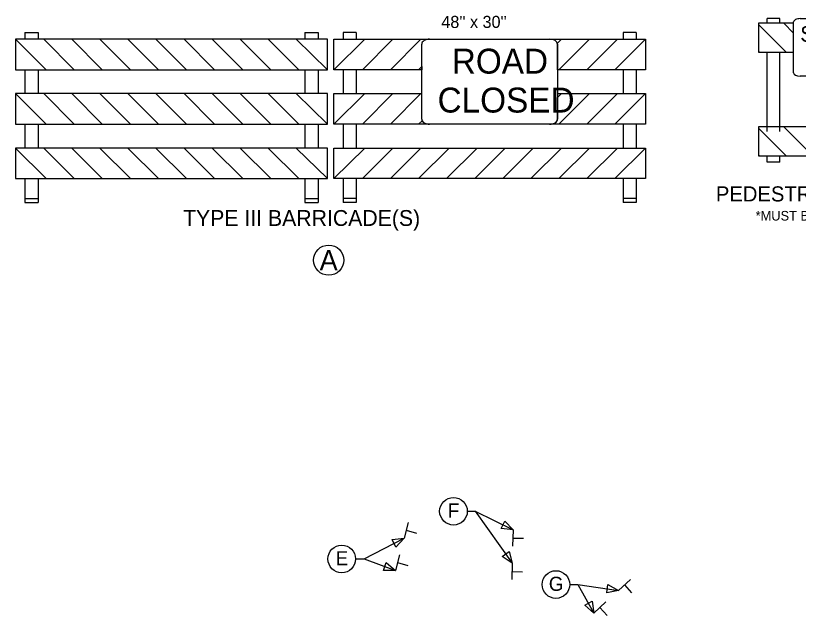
# Model space of a CAD drawing. Extents: x 2157572 to 5059327, y 715220 to 1674494.
# Drawn here: x 2159643 to 2163528, y 715966 to 718941 of the extents above; entities that cross this region are included whole.
import ezdxf

# ---------------------------------------------------------------- set-up
doc = ezdxf.new("R2010")
doc.units = 0
for name, color, linetype in [('Exist Cultural Church Label', 7, 'Continuous'), ('Exist Hydrographic Creek Single Shore Label', 7, 'Continuous'), ('Exist Road Primary US Structure Standard Bridge Number Label', 7, 'Continuous'), ('Exist Road Secondary Structure Culvert Number Label', 7, 'Continuous'), ('Level 51', 7, 'Continuous'), ('Map Preparation County Base Legend Hangar on Field', 7, 'Continuous'), ('Map Preparation County Base Legend Highway Garage or Maintenance Office', 7, 'Continuous'), ('Map Preparation County Base Legend Marked Auxillary Field', 7, 'Continuous'), ('Map Preparation County Base Legend Rest Area', 7, 'Continuous'), ('Map Preparation County North Arrow Shadow', 7, 'Continuous')]:
    doc.layers.add(name, color=color, linetype=linetype)

# ---------------------------------------------------------------- blocks, each defined once
blk = doc.blocks.new('PEDBARRSWCLOSED')
at = {"layer": 'Map Preparation County Base Legend Hangar on Field'}
for p, q in [((26.5, 0), (0, 0)), ((0, 0), (-26.5, 0))]:
    blk.add_line(p, q, dxfattribs=at)
for points in [[(-26.5, 30), (0, 30)], [(0, 30), (26.5, 30)], [(-30, 1.75), (-30, 28.25)], [(30, 28.25), (30, 1.75)]]:
    blk.add_lwpolyline(points, dxfattribs=at)
for centre, major_axis, start_param, end_param in [((-26.5, 28.25), (-3.5, 0), 4.712162, 6.283185), ((26.5, 28.25), (3.5, 0), 0, 1.570796), ((-26.5, 1.75), (-3.5, 0), 0, 1.570796), ((26.5, 1.75), (-3.5, 0), 1.570796, 3.141593)]:
    blk.add_ellipse(centre, major_axis=major_axis, ratio=0.5, start_param=start_param, end_param=end_param, dxfattribs=at)
at = {"layer": 'Map Preparation County Base Legend Marked Auxillary Field'}
for p, q in [((-37.19, 30), (-43.76, 30)), ((-43.76, 27.64), (-43.76, 30)), ((-37.19, 27.64), (-37.19, 30)), ((43.76, 30), (37.19, 30)), ((37.19, 27.64), (37.19, 30)), ((43.76, 27.64), (43.76, 30.06)), ((-48.36, 27.64), (-48.36, 12.46)), ((-30, 27.64), (-48.36, 27.64)), ((-35.14, 27.64), (-48.36, 27.64)), ((-30, 22.5), (-35.14, 27.64)), ((30, 21.58), (36.06, 27.64)), ((48.36, 27.64), (30, 27.64)), ((36.06, 27.64), (48.36, 27.64)), ((48.36, 12.46), (48.36, 27.64)), ((-47.82, 12.46), (-48.36, 13.01)), ((-48.36, 12.46), (-47.82, 12.46)), ((-48.36, 12.46), (-30, 12.46)), ((-43.76, -14.53), (-43.76, 12.46)), ((-37.19, -14.53), (-37.19, 12.46)), ((30, 12.46), (48.36, 12.46)), ((37.19, -14.53), (37.19, 12.46)), ((43.76, -14.53), (43.76, 12.46)), ((-43.76, -28.8), (-43.76, -14.53)), ((-37.19, -28.7), (-37.19, -14.53)), ((37.19, -33.18), (37.19, -14.53)), ((43.76, -32.25), (43.76, -14.53)), ((-48.36, -26.35), (-48.36, -41.53)), ((48.36, -26.35), (-48.36, -26.35)), ((-35.14, -26.35), (-48.36, -26.35)), ((-19.97, -41.53), (-35.14, -26.35)), ((-6.04, -41.53), (-21.21, -26.35)), ((-21.21, -26.35), (-7.29, -26.35)), ((-7.29, -26.35), (0.46, -34.1)), ((0.46, -34.1), (8.21, -26.35)), ((22.13, -26.35), (6.96, -41.53)), ((8.21, -26.35), (22.13, -26.35)), ((20.89, -41.53), (36.06, -26.35)), ((36.06, -26.35), (48.36, -26.35)), ((48.36, -41.53), (48.36, -26.35)), ((65.44, -34.49), (65.44, -41.53)), ((-47.82, -41.53), (-48.36, -40.98)), ((-48.36, -41.53), (-47.82, -41.53)), ((-48.36, -41.53), (48.36, -41.53)), ((-43.76, -44.81), (-43.76, -41.53)), ((-37.19, -44.81), (-43.76, -44.81)), ((-37.19, -44.81), (-37.19, -41.53)), ((-33.89, -41.53), (-19.97, -41.53)), ((6.96, -41.53), (-6.96, -41.53)), ((34.81, -41.53), (20.89, -41.53)), ((37.19, -44.81), (37.19, -41.53)), ((43.76, -44.81), (37.19, -44.81)), ((43.76, -44.81), (43.76, -41.53)), ((51.11, -44.81), (66.83, -44.81)), ((53.37, -41.53), (66.83, -41.53)), ((65.44, -44.81), (65.44, -51.17))]:
    blk.add_line(p, q, dxfattribs=at)
for points in [[(-48.36, 27.64), (-48.36, 26.93), (-33.89, 12.46)], [(48.36, 27.64), (48.36, 26.01), (34.81, 12.46)], [(-33.89, 12.46), (-30, 12.46), (-30, 22.5)], [(34.81, 12.46), (30, 12.46), (30, 21.58)], [(-48.36, -26.35), (-48.36, -27.06), (-33.89, -41.53)], [(48.36, -26.35), (48.36, -27.98), (34.81, -41.53)]]:
    blk.add_lwpolyline(points, dxfattribs=at)
at = {"layer": 'Map Preparation County Base Legend Hangar on Field'}
for s, p in [('SIDEWALK', (-26.54, 17.9)), ('CLOSED', (-21.11, 4.07))]:
    blk.add_text(s, height=8.172, dxfattribs=at).set_placement(p)
at = {"layer": 'Map Preparation County Base Legend Marked Auxillary Field'}
for s, height, p in [('2" MAX', 6, (70.36, -45.51)), ('PEDESTRIAN BARRICADE', 7.8816, (-70.5, -65.23)), ('*MUST BE ADA-COMPLIANT*', 5, (-49.77, -75.16))]:
    blk.add_text(s, height=height, dxfattribs=at).set_placement(p)

msp = doc.modelspace()

# ---------------------------------------------------------------- linework, layer by layer
at = {"layer": 'Exist Cultural Church Label'}
for centre in [(2161816.1, 716482.5), (2161261.4, 716246), (2162324.6, 716119)]:
    msp.add_circle(centre, 68.6, dxfattribs=at)
at = {"layer": 'Exist Road Secondary Structure Culvert Number Label'}
for p, q in [((2159688.5, 718856.9), (2159754.2, 718856.9)), ((2159688.5, 718856.9), (2159688.5, 718824)), ((2159754.2, 718856.9), (2159754.2, 718824)), ((2161078.3, 718856.9), (2161144, 718856.9)), ((2161078.3, 718856.9), (2161078.3, 718824)), ((2161144, 718856.9), (2161144, 718824)), ((2161333.6, 718856.9), (2161267.9, 718856.9)), ((2161267.9, 718856.9), (2161267.9, 718824)), ((2161333.6, 718856.9), (2161333.6, 718824)), ((2162723.4, 718856.9), (2162657.7, 718856.9)), ((2162657.7, 718856.9), (2162657.7, 718824)), ((2162723.4, 718856.9), (2162723.4, 718824)), ((2161190, 718824), (2159642.5, 718824)), ((2159642.5, 718824), (2159642.5, 718672.3)), ((2159781.8, 718824), (2159642.5, 718824)), ((2159642.5, 718824), (2159794.3, 718672.3)), ((2159933.5, 718672.3), (2159781.8, 718824)), ((2160060.3, 718824), (2159921, 718824)), ((2159921, 718824), (2160072.7, 718672.3)), ((2160212, 718672.3), (2160060.3, 718824)), ((2160338.7, 718824), (2160199.5, 718824)), ((2160199.5, 718824), (2160351.2, 718672.3)), ((2160490.5, 718672.3), (2160338.7, 718824)), ((2160617.9, 718824), (2160478.6, 718824)), ((2160478.6, 718824), (2160630.4, 718672.3)), ((2160769.6, 718672.3), (2160617.9, 718824)), ((2160896.4, 718824), (2160757.1, 718824)), ((2160757.1, 718824), (2160908.8, 718672.3)), ((2161048.1, 718672.3), (2160896.4, 718824)), ((2161190, 718824), (2161035.6, 718824)), ((2161035.6, 718824), (2161190, 718672.3)), ((2161190, 718672.3), (2161190, 718824)), ((2161190, 718672.3), (2161190, 718824)), ((2161221.9, 718824), (2162769.4, 718824)), ((2161221.9, 718672.3), (2161221.9, 718824)), ((2161221.9, 718672.3), (2161221.9, 718824)), ((2161221.9, 718824), (2161376.3, 718824)), ((2161376.3, 718824), (2161221.9, 718672.3)), ((2161363.8, 718672.3), (2161515.5, 718824)), ((2161654.8, 718824), (2161503, 718672.3)), ((2161515.5, 718824), (2161654.8, 718824)), ((2162332.1, 718804.5), (2162351.6, 718824)), ((2162490.9, 718824), (2162339.2, 718672.3)), ((2162351.6, 718824), (2162490.9, 718824)), ((2162478.4, 718672.3), (2162630.1, 718824)), ((2162769.4, 718824), (2162617.6, 718672.3)), ((2162630.1, 718824), (2162769.4, 718824)), ((2162769.4, 718824), (2162769.4, 718672.3)), ((2162333, 718672.3), (2162333, 718799.5)), ((2159642.5, 718672.3), (2161190, 718672.3)), ((2159688.5, 718672.3), (2159688.5, 718554.1)), ((2159754.2, 718672.3), (2159754.2, 718554.1)), ((2159794.3, 718672.3), (2159933.5, 718672.3)), ((2160072.7, 718672.3), (2160212, 718672.3)), ((2160351.2, 718672.3), (2160490.5, 718672.3)), ((2160630.4, 718672.3), (2160769.6, 718672.3)), ((2160908.8, 718672.3), (2161048.1, 718672.3)), ((2161078.3, 718672.3), (2161078.3, 718554.1)), ((2161144, 718672.3), (2161144, 718554.1)), ((2161658.3, 718672.3), (2161221.9, 718672.3)), ((2161267.9, 718672.3), (2161267.9, 718554.1)), ((2161333.6, 718672.3), (2161333.6, 718554.1)), ((2161503, 718672.3), (2161363.8, 718672.3)), ((2161642.3, 718672.3), (2161658.3, 718688.3)), ((2161658.3, 718672.3), (2161642.3, 718672.3)), ((2161658.3, 718688.3), (2161658.3, 718672.3)), ((2162339.2, 718672.3), (2162333, 718672.3)), ((2162769.4, 718672.3), (2162333, 718672.3)), ((2162617.6, 718672.3), (2162478.4, 718672.3)), ((2162657.7, 718672.3), (2162657.7, 718554.1)), ((2162723.4, 718672.3), (2162723.4, 718554.1)), ((2161190, 718554.1), (2159642.5, 718554.1)), ((2159642.5, 718554.1), (2159642.5, 718402.4)), ((2159781.8, 718554.1), (2159642.5, 718554.1)), ((2159642.5, 718554.1), (2159794.3, 718402.4)), ((2159933.5, 718402.4), (2159781.8, 718554.1)), ((2160060.3, 718554.1), (2159921, 718554.1)), ((2159921, 718554.1), (2160072.7, 718402.4)), ((2160212, 718402.4), (2160060.3, 718554.1)), ((2160338.7, 718554.1), (2160199.5, 718554.1)), ((2160199.5, 718554.1), (2160351.2, 718402.4)), ((2160490.5, 718402.4), (2160338.7, 718554.1)), ((2160617.9, 718554.1), (2160478.6, 718554.1)), ((2160478.6, 718554.1), (2160630.4, 718402.4)), ((2160769.6, 718402.4), (2160617.9, 718554.1)), ((2160896.4, 718554.1), (2160757.1, 718554.1)), ((2160757.1, 718554.1), (2160908.8, 718402.4)), ((2161048.1, 718402.4), (2160896.4, 718554.1)), ((2161190, 718554.1), (2161035.6, 718554.1)), ((2161035.6, 718554.1), (2161190, 718402.4)), ((2161190, 718402.4), (2161190, 718554.1)), ((2161190, 718402.4), (2161190, 718554.1)), ((2161221.9, 718402.4), (2161221.9, 718554.1)), ((2161221.9, 718402.4), (2161221.9, 718554.1)), ((2161221.9, 718554.1), (2161376.3, 718554.1)), ((2161376.3, 718554.1), (2161221.9, 718402.4)), ((2161221.9, 718554.1), (2161658.3, 718554.1)), ((2161363.8, 718402.4), (2161515.5, 718554.1)), ((2161654.8, 718554.1), (2161503, 718402.4)), ((2161515.5, 718554.1), (2161654.8, 718554.1)), ((2162333, 718535.4), (2162351.6, 718554.1)), ((2162333, 718554.1), (2162769.4, 718554.1)), ((2162333, 718427), (2162333, 718535.4)), ((2162490.9, 718554.1), (2162339.2, 718402.4)), ((2162351.6, 718554.1), (2162490.9, 718554.1)), ((2162478.4, 718402.4), (2162630.1, 718554.1)), ((2162769.4, 718554.1), (2162617.6, 718402.4)), ((2162630.1, 718554.1), (2162769.4, 718554.1)), ((2162769.4, 718554.1), (2162769.4, 718402.4)), ((2161642.3, 718402.4), (2161659.9, 718420)), ((2159642.5, 718402.4), (2161190, 718402.4)), ((2159688.5, 718402.4), (2159688.5, 718284.2)), ((2159754.2, 718402.4), (2159754.2, 718284.2)), ((2159794.3, 718402.4), (2159933.5, 718402.4)), ((2160072.7, 718402.4), (2160212, 718402.4)), ((2160351.2, 718402.4), (2160490.5, 718402.4)), ((2160630.4, 718402.4), (2160769.6, 718402.4)), ((2160908.8, 718402.4), (2161048.1, 718402.4)), ((2161078.3, 718402.4), (2161078.3, 718284.2)), ((2161144, 718402.4), (2161144, 718284.2)), ((2162769.4, 718402.4), (2161221.9, 718402.4)), ((2161267.9, 718402.4), (2161267.9, 718284.2)), ((2161333.6, 718402.4), (2161333.6, 718284.2)), ((2161503, 718402.4), (2161363.8, 718402.4)), ((2161697.7, 718402.4), (2161642.3, 718402.4)), ((2162293.6, 718402.4), (2161697.7, 718402.4)), ((2162339.2, 718402.4), (2162293.9, 718402.4)), ((2162617.6, 718402.4), (2162478.4, 718402.4)), ((2162657.7, 718402.4), (2162657.7, 718284.2)), ((2162723.4, 718402.4), (2162723.4, 718284.2)), ((2159781.8, 718284.2), (2159642.5, 718284.2)), ((2159642.5, 718284.2), (2159794.3, 718132.4)), ((2161190, 718284.2), (2159642.5, 718284.2)), ((2159642.5, 718284.2), (2159642.5, 718132.4)), ((2159933.5, 718132.4), (2159781.8, 718284.2)), ((2160060.3, 718284.2), (2159921, 718284.2)), ((2159921, 718284.2), (2160072.7, 718132.4)), ((2160212, 718132.4), (2160060.3, 718284.2)), ((2160338.7, 718284.2), (2160199.5, 718284.2)), ((2160199.5, 718284.2), (2160351.2, 718132.4)), ((2160490.5, 718132.4), (2160338.7, 718284.2)), ((2160617.9, 718284.2), (2160478.6, 718284.2)), ((2160478.6, 718284.2), (2160630.4, 718132.4)), ((2160769.6, 718132.4), (2160617.9, 718284.2)), ((2160896.4, 718284.2), (2160757.1, 718284.2)), ((2160757.1, 718284.2), (2160908.8, 718132.4)), ((2161048.1, 718132.4), (2160896.4, 718284.2)), ((2161190, 718284.2), (2161035.6, 718284.2)), ((2161035.6, 718284.2), (2161190, 718132.4)), ((2161190, 718132.4), (2161190, 718284.2)), ((2161190, 718132.4), (2161190, 718284.2)), ((2161221.9, 718132.4), (2161221.9, 718284.2)), ((2161221.9, 718284.2), (2161376.3, 718284.2)), ((2161376.3, 718284.2), (2161221.9, 718132.4)), ((2161221.9, 718284.2), (2162769.4, 718284.2)), ((2161221.9, 718132.4), (2161221.9, 718284.2)), ((2161363.8, 718132.4), (2161515.5, 718284.2)), ((2161654.8, 718284.2), (2161503, 718132.4)), ((2161515.5, 718284.2), (2161654.8, 718284.2)), ((2161642.3, 718132.4), (2161794, 718284.2)), ((2161933.3, 718284.2), (2161781.5, 718132.4)), ((2161794, 718284.2), (2161933.3, 718284.2)), ((2161921.4, 718132.4), (2162073.2, 718284.2)), ((2162212.4, 718284.2), (2162060.7, 718132.4)), ((2162073.2, 718284.2), (2162212.4, 718284.2)), ((2162199.9, 718132.4), (2162351.6, 718284.2)), ((2162490.9, 718284.2), (2162339.2, 718132.4)), ((2162351.6, 718284.2), (2162490.9, 718284.2)), ((2162478.4, 718132.4), (2162630.1, 718284.2)), ((2162769.4, 718284.2), (2162617.6, 718132.4)), ((2162630.1, 718284.2), (2162769.4, 718284.2)), ((2162769.4, 718284.2), (2162769.4, 718132.4)), ((2159642.5, 718132.4), (2161190, 718132.4)), ((2159688.5, 718132.4), (2159688.5, 718014.2)), ((2159754.2, 718132.4), (2159754.2, 718014.2)), ((2159794.3, 718132.4), (2159933.5, 718132.4)), ((2160072.7, 718132.4), (2160212, 718132.4)), ((2160351.2, 718132.4), (2160490.5, 718132.4)), ((2160630.4, 718132.4), (2160769.6, 718132.4)), ((2160908.8, 718132.4), (2161048.1, 718132.4)), ((2161078.3, 718132.4), (2161078.3, 718014.2)), ((2161144, 718132.4), (2161144, 718014.2)), ((2162769.4, 718132.4), (2161221.9, 718132.4)), ((2161267.9, 718132.4), (2161267.9, 718014.2)), ((2161333.6, 718132.4), (2161333.6, 718014.2)), ((2161503, 718132.4), (2161363.8, 718132.4)), ((2161781.5, 718132.4), (2161642.3, 718132.4)), ((2162060.7, 718132.4), (2161921.4, 718132.4)), ((2162339.2, 718132.4), (2162199.9, 718132.4)), ((2162617.6, 718132.4), (2162478.4, 718132.4)), ((2162657.7, 718132.4), (2162657.7, 718014.2)), ((2162723.4, 718132.4), (2162723.4, 718014.2)), ((2159688.5, 718033.9), (2159754.2, 718033.9)), ((2161078.3, 718033.9), (2161144, 718033.9)), ((2161333.6, 718033.9), (2161267.9, 718033.9)), ((2162723.4, 718033.9), (2162657.7, 718033.9)), ((2159688.5, 718014.2), (2159754.2, 718014.2)), ((2161078.3, 718014.2), (2161144, 718014.2)), ((2161333.6, 718014.2), (2161267.9, 718014.2)), ((2162723.4, 718014.2), (2162657.7, 718014.2))]:
    msp.add_line(p, q, dxfattribs=at)
for points in [[(2161697.7, 718824), (2162293.6, 718824)], [(2161658.3, 718427), (2161658.3, 718799.5)], [(2162333, 718799.5), (2162333, 718427)]]:
    msp.add_lwpolyline(points, dxfattribs=at)
for centre, major_axis, start_param, end_param in [((2161697.7, 718799.5), (-39.4, 0), 4.712162, 6.283185), ((2162293.6, 718799.5), (39.4, 0), 0, 1.570796), ((2162293.6, 718799.5), (39.4, 0), 6.283185, 6.491582), ((2161697.7, 718427), (-39.4, 0), 0, 1.571024), ((2161697.7, 718427), (-39.4, 0), 0.287132, 1.570688), ((2162293.6, 718427), (-39.4, 0), 1.570796, 3.141593), ((2162293.6, 718427), (39.4, 0), 4.712389, 6.283185)]:
    msp.add_ellipse(centre, major_axis=major_axis, ratio=0.625, start_param=start_param, end_param=end_param, dxfattribs=at)
at = {"layer": 'Level 51'}
for p, q in [((2161884.7, 716482.5), (2161924.3, 716482.5)), ((2161924.3, 716482.5), (2162111.7, 716390.4)), ((2161924.3, 716482.5), (2162107.8, 716224.4)), ((2161373.3, 716246), (2161570.7, 716349.2)), ((2161330, 716246), (2161373.3, 716246)), ((2161373.3, 716246), (2161528.1, 716188.7)), ((2162393.2, 716119), (2162432.8, 716119)), ((2162432.8, 716119), (2162635, 716090)), ((2162432.8, 716119), (2162513.5, 715977.5))]:
    msp.add_line(p, q, dxfattribs=at)
for points in [[(2162052.2, 716396.5), (2162070.5, 716433.7), (2162111.7, 716390.4)], [(2161530.7, 716304.8), (2161511.4, 716341.6), (2161570.7, 716349.2)], [(2162058.4, 716258.1), (2162092.2, 716282.1), (2162107.8, 716224.4)], [(2161468.3, 716188.7), (2161482.7, 716227.6), (2161528.1, 716188.7)], [(2162576.6, 716077.4), (2162582.5, 716118.5), (2162635, 716090)], [(2162467.7, 716015.9), (2162503.8, 716036.5), (2162513.5, 715977.5)]]:
    msp.add_lwpolyline(points, close=True, dxfattribs=at)
at = {"layer": 'Map Preparation County Base Legend Highway Garage or Maintenance Office'}
for centre in [(2161816.1, 716482.5), (2161261.4, 716246), (2162324.6, 716119)]:
    msp.add_circle(centre, 68.6, dxfattribs=at)
at = {"layer": 'Map Preparation County Base Legend Rest Area'}
msp.add_circle((2161196.7, 717728.1), 75, dxfattribs=at)
at = {"layer": 'Map Preparation County North Arrow Shadow'}
for p, q in [((2161591.5, 716427.5), (2161570.7, 716349.2)), ((2161581, 716388), (2161631.8, 716374.5)), ((2162111.7, 716390.4), (2162109.8, 716309.4)), ((2162110.7, 716349.6), (2162163.2, 716348.3)), ((2161548.9, 716267), (2161528.1, 716188.7)), ((2161538.4, 716227.6), (2161589.1, 716214.1)), ((2162107.8, 716224.4), (2162105.8, 716143.4)), ((2162106.8, 716183.6), (2162159.3, 716182.3)), ((2162695.2, 716144.3), (2162635, 716090)), ((2162664.8, 716116.9), (2162700, 716078)), ((2162573, 716032.5), (2162513.5, 715977.5)), ((2162543, 716004.8), (2162578.7, 715966.2))]:
    msp.add_line(p, q, dxfattribs=at)

# ---------------------------------------------------------------- block references
at = {"layer": 'Exist Hydrographic Creek Single Shore Label', "xscale": 9.525466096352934, "yscale": 9.525466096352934, "rotation": -1.2796055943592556e-10}
msp.add_blockref('PEDBARRSWCLOSED', (2163790.2, 718640.5), dxfattribs=at)

# ---------------------------------------------------------------- texts
at = {"layer": 'Exist Road Primary US Structure Standard Bridge Number Label'}
for s, p in [('F', (2161788.2, 716451.1)), ('E', (2161231.1, 716214.5)), ('G', (2162289.4, 716087.6))]:
    msp.add_text(s, height=70, dxfattribs=at).set_placement(p)
at = {"layer": 'Exist Road Secondary Structure Culvert Number Label'}
for s, height, p in [("48'' x 30''", 60, (2161755.9, 718880)), ('ROAD', 123.69, (2161807.7, 718653.4)), ('CLOSED', 123.69, (2161737.1, 718460.3)), ('TYPE III BARRICADE(S)', 78.816, (2160473.5, 717897.8))]:
    msp.add_text(s, height=height, rotation=360, dxfattribs=at).set_placement(p)
at = {"layer": 'Map Preparation County Base Legend Rest Area'}
msp.add_text('A', height=100, rotation=360, dxfattribs=at).set_placement((2161151.8, 717678.1))

doc.saveas('drawing.dxf')
